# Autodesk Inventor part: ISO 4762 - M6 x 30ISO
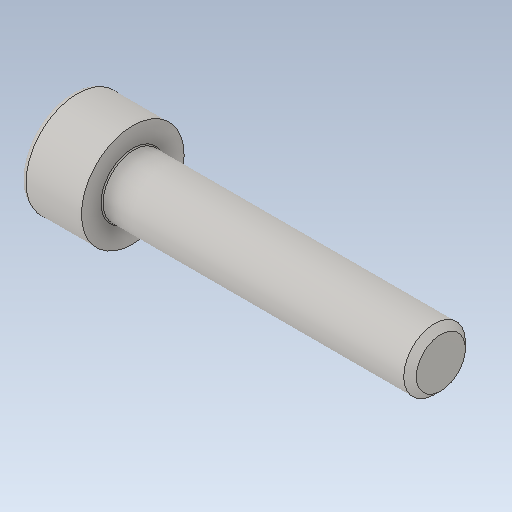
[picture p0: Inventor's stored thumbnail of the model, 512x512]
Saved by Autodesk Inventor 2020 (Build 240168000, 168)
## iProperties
Created: 2015-11
Part Number: ISO 4762 - M6 x 30ISO
Material: Ogólny
Document SubType Name: Modeling
Designer: Tomasz
Density: 1 g/cm^3
Appearance: Domyślna
Sending System: SolidWorks 2017
Last Author: Tomasz
Last Saved: 2017-09-27
Author: Tomasz
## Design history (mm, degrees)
feature "Imported1"
node "Bryła1"
